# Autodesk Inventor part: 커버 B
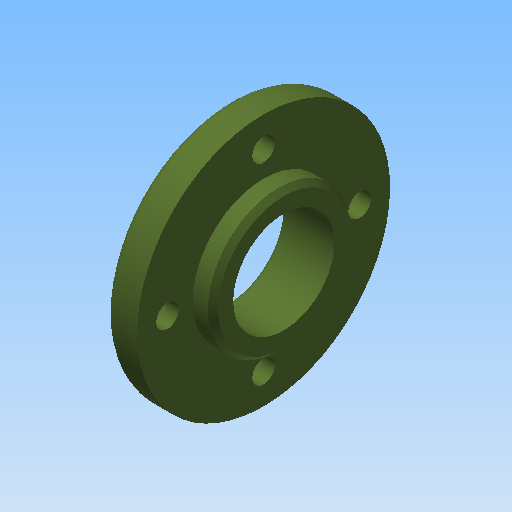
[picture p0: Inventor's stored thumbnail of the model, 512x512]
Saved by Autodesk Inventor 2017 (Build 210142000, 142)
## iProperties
Created: 2019-01
Part Number: 커버 B
Material: 알루미늄 6061
Document SubType Name: Modeling
Designer: mduedu
Density: 2.71 g/cm^3
Mass: 30.6342 g
Surface Area: 56.15 cm^2
Volume: 11.3041 cm^3
Appearance: 올리브 녹색
Author: mduedu
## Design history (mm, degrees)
sketch "스케치1"
  geometry: L1 (0, 0)-(7, 0); L2 (7, 0)-(7, 25); L3 (7, 25)-(0, 25); L4 (0, 25)-(0, 0); L5 (7, 0)-(11, 0); L6 (11, 0)-(11, 14); L7 (11, 14)-(7, 14); L8 (7, 14)-(7, 0)
  constraints: 16 end point, 4 parallel, 2 horizontal, 2 perpendicular
  dimensions: "d0" = 50 diameter of L3 L1; "d2" = 11 distance between parallel lines of L6 L4; "d3" = 7 distance of L2.end L3.end; "d4" = 28 diameter of L7 L5
revolve "회전1" sketch "스케치1" stored, may be unused: angle "d5" = 90 deg
sketch "스케치2"
  geometry: C1 r 10 at (0, 0); 1 further point
  constraints: 1 centre point, 1 coincident
  dimensions: "d6" = 20 diameter of C1
extrude "돌출1" cut sketch "스케치2" stored distance "d7" = 10; taper "d8" = 0 deg
chamfer "모따기1" distance "d9" = 1; stored, may be unused: second distance "d10" = 2, angle "d11" = 45 deg
fillet "모깎기1" dims "d12" = 3
sketch "스케치3" dims "d13" = 38
  geometry: 6 further points
  constraints: 2 vertical alignment, 1 coincident, 7 other
  dimensions: "d16" = 360 deg dimension on point (0, 0) point (0, 19) (derived)
chamfer "모따기2" distance "d18" = 1; stored, may be unused: second distance "d19" = 2, angle "d20" = 45 deg
sketch "스케치4"
  geometry: 4 further points
  constraints: 4 other
hole "구멍1" sketch "스케치4" at (-19, 0), (0, -19), (19, 0), (0, 19) diameter "d21" = 4.5; stored, may be unused: countersink angle "d25" = 90 deg, drill point angle "d27" = 0 deg; dims "d22" = 6, "d23" = 8, "d24" = 4.6, "d26" = 8
node "솔리드1"
